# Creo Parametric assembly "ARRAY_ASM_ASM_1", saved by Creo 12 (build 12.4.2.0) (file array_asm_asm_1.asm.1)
Units: Custom; MM, KILOGRAM, SECS

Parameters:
  PTC_WM_ITERATION = "0"
  PTC_WM_VERSION = "-.0"
  PTC_WM_LIFECYCLE_STATE = "In Work"
  PTC_WM_LIFECYCLE = "MO_CADDocument"
  PTC_WM_CREATED_BY = "Maximilian Roepper (Z0017RMS: MO)"
  PTC_WM_CREATED_ON = "18-Sep-26 11:36:42 AM"
  PTC_WM_MODIFIED_BY = "Maximilian Roepper (Z0017RMS: MO)"
  PTC_WM_MODIFIED_ON = "18-Sep-26 11:36:46 AM"
  PDMLINKNUMBER = "PDM000071455086"
  PTC_WM_NUMBER = "PDM000071455086"

Other parameters: WEIGHT, WEIGHT_FACTOR, WEIGHT_ADD, MC_ERRORS, SUPPLIER

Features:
  1. coordinate system
  2. imported feature
  3. component "CORPS_PRT_1"
  4. component "CORPS_PRT_1"
  5. component "CORPS_PRT_1"
  6. component "CORPS_PRT_1"
  7. component "CORPS_PRT_1"
  8. component "CORPS_PRT_1"
  9. component "CORPS_PRT_1"
  10. component "CORPS_PRT_1"
  11. component "CORPS_PRT_1"
  12. component "CORPS_PRT_1"
  13. component "CORPS_PRT_1"
  14. component "CORPS_PRT_1"
  15. component "CORPS_PRT_1"
  16. component "CORPS_PRT_1"
  17. component "CORPS_PRT_1"
  18. component "CORPS_PRT_1"
  19. component "CORPS_PRT_1"
  20. component "CORPS_PRT_1"
  21. component "CORPS_PRT_1"
  22. component "CORPS_PRT_1"
  23. component "CORPS_PRT_1"
  24. component "CORPS_PRT_1"
  25. component "CORPS_PRT_1"
  26. component "CORPS_PRT_1"
  27. component "CORPS_PRT_1"
  28. component "CORPS_PRT_1"
  29. component "CORPS_PRT_1"
  30. component "CORPS_PRT_1"
  31. component "CORPS_PRT_1"
  32. component "CORPS_PRT_1"

Other named items: DRW_VIEW_ORG, ROUGH-GROB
